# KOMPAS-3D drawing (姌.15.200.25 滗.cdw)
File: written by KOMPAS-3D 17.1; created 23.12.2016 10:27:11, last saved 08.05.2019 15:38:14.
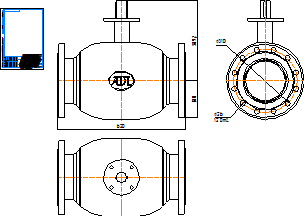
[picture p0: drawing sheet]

Sheet 1: A4, portrait

Title block, sheet 1: name: КШ.15.200.25 фф; material: Внимание! Данный продукт является объектом авторского права ООО «Торговый Дом АДЛ». / Запрещается изменение, копирование, распространение / (в том числе путем копирования на другие сайты и ресурсы в Интернете) / или любое иное использование информации и объектов без предварительного / согласия правообладателя (ООО «Торговый Дом АДЛ»).; sheets: 1; organisation: ООО "Торговый дом АДЛ"; sheet format: A4; stored path: C:\Users\tra\Desktop\2д чертежи\Шаровые краны БИВАЛ\КШ_Бивал_серия_14_15\KOMPAS_2D\КШ.15.200.25 фф.cdw

Views: Вид 1, Проекционный вид 2, Проекционный вид 3
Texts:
  Klimkovich
  ADL
Dimensions and other numbers on the sheet: 620; 389,2; 180; 310; 26; 12 Отв.; 1:1; 1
